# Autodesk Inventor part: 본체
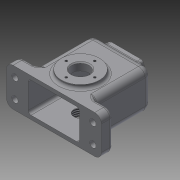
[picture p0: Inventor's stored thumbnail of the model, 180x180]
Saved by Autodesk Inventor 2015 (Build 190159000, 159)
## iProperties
Created: 2023-12
Part Number: 본체
Material: 일반
Document SubType Name: Modeling
Designer: 104-1
Density: 1 g/cm^3
Appearance: 기본값
Mass: 83.567 g
Surface Area: 378.551 cm^2
Volume: 83.567 cm^3
Author: 104-1
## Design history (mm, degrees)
sketch "스케치1"
  geometry: L1 (31, 20)-(-31, 20); L2 (-31, 20)-(-31, -20); L3 (-31, -20)-(31, -20); L4 (31, -20)-(31, 20); L5 (31, 20)-(-31, -20); L6 (-31, 20)-(31, -20); 1 further point
  constraints: 12 end point, 2 midpoint, 2 parallel, 1 horizontal, 1 perpendicular
  dimensions: "d0" = 62 distance of L2.end L3.end; "d1" = 40 distance of L1.end L2.end
extrude "돌출1" new body sketch "스케치1" distance "d2" = 72; taper "d3" = 0 deg
feature "쉘1" dims "d4" = 4
sketch "스케치2"
  geometry: L1 (-31, 20)-(31, 20) reference; L2 (-31, -20)-(-31, 20) reference; L3 (31, -20)-(-31, -20) reference; L4 (31, 20)-(31, -20) reference; L5 (-50, -20)-(50, -20); L6 (50, -20)-(50, 20); L7 (50, 20)-(-50, 20); L8 (-50, 20)-(-50, -20); L9 (-50, -20)-(50, 20); L10 (50, -20)-(-50, 20); 1 further point
  constraints: 12 end point, 2 midpoint, 2 parallel, 1 horizontal, 1 perpendicular
  dimensions: "d5" = 40 distance of L5.end L6.end; "d6" = 100 distance of L6.end L7.end
extrude "돌출2" join sketch "스케치2" distance "d7" = 12; taper "d8" = 0 deg
sketch "스케치4"
  geometry: L1 (-19, -72)-(81, -72) reference; C1 r 20 at (31, -44); 2 further points
  constraints: 1 centre point, 1 midpoint, 1 vertical alignment
  dimensions: "d9" = 40 diameter of C1; "d10" = 28 distance of point (31, -72) C1.centre
extrude "돌출3" join sketch "스케치4" distance "d11" = 4; taper "d12" = 0 deg
sketch "스케치5"
  geometry: C1 r 12 at (31, -44); 1 further point
  constraints: 1 centre point
  dimensions: "d13" = 28 distance of point (31, -72) C1.centre; "d14" = 24 diameter of C1
extrude "돌출4" join sketch "스케치5" distance "d15" = 4; taper "d16" = 0 deg
sketch "스케치6"
  geometry: C1 r 20 at (0, 0) reference; 2 further points
  constraints: 1 coincident
hole "구멍1" sketch "스케치6" at (0, 0) diameter "d17" = 18; stored, may be unused: countersink angle "d21" = 90 deg, drill point angle "d23" = 118 deg; dims "d18" = 6, "d19" = 4, "d20" = 2, "d22" = 8
sketch "스케치7"
  geometry: C1 r 9 at (0, 0) reference; 2 further points
  dimensions: "d24" = 15 distance of C1.centre point (0, 15)
hole "구멍2" sketch "스케치7" at (0, 15) diameter "d25" = 2.459; stored, may be unused: countersink angle "d29" = 90 deg, drill point angle "d31" = 118 deg; dims "d26" = 6, "d27" = 4, "d28" = 2, "d30" = 8.8
sketch "스케치8"
  geometry: C1 r 12 at (0, 0) reference; 2 further points
  constraints: 1 coincident
hole "구멍3" sketch "스케치8" at (0, 0) diameter "d35" = 13.835; stored, may be unused: countersink angle "d39" = 90 deg, drill point angle "d41" = 118 deg; dims "d36" = 32, "d37" = 4, "d38" = 2, "d40" = 10
sketch "스케치9"
  geometry: L1 (0, 0)-(62, 0) reference; L2 (11, -24)-(51, -24); L3 (51, -24)-(51, 0); L4 (51, 0)-(11, 0); L5 (11, 0)-(11, -24); L6 (11, -24)-(51, 0); L7 (51, -24)-(11, 0); C1 r 12 at (31, -44) reference; 3 further points
  constraints: 12 end point, 3 midpoint, 2 parallel, 1 collinear, 1 horizontal, 1 perpendicular, 1 vertical alignment
  dimensions: "d42" = 24 distance of L2.end L3.end; "d43" = 40 distance of L2.start L2.end
extrude "돌출5" join sketch "스케치9" distance "d44" = 4; taper "d45" = 0 deg
sketch "스케치10"
  geometry: L1 (11, -24)-(51, -24) reference; L2 (51, 0)-(11, 0) reference; L3 (31, 0)-(31, -24); 3 further points
  constraints: 2 end point, 2 midpoint, 1 symmetric about line
  dimensions: "d46" = 28 distance of point (45, -6) point (17, -6); "d47" = 6 distance from line of L2 point (17, -6)
hole "구멍4" sketch "스케치10" at (17, -6), (45, -6) diameter "d48" = 2.459; stored, may be unused: countersink angle "d52" = 90 deg, drill point angle "d54" = 118 deg; dims "d49" = 6, "d50" = 4, "d51" = 2, "d53" = 8.8
sketch "스케치11"
  geometry: L1 (-20, 24)-(20, 24) reference; L2 (17.321, 3)-(-17.321, 3); L3 (-17.321, -17)-(17.321, -17); L4 (17.321, 3)-(-17.321, -17); L5 (-17.321, 3)-(17.321, -17); A1 r 20 centre (0, -7) between (17.321, -17) and (17.321, 3); A2 r 20 centre (0, -7) between (-17.321, 3) and (-17.321, -17); 3 further points
  constraints: 8 end point, 4 point on circle, 3 midpoint, 2 centre point, 1 coincident, 1 horizontal, 1 parallel, 1 vertical alignment
  dimensions: "d56" = 31 distance from line of L1 point (0, -7); "d57" = 20 radius of A2; "d58" = 20 distance between parallel lines of L2 L3
extrude "돌출6" join sketch "스케치11" distance "d59" = 4; taper "d60" = 0 deg
sketch "스케치12"
  geometry: L1 (17.321, 3)-(-17.321, 3) reference; L2 (-17.321, -17)-(17.321, -17) reference; L3 (0, -17)-(0, 3); 4 further points
  constraints: 3 midpoint, 2 end point, 1 horizontal alignment, 1 symmetric about line
  dimensions: "d61" = 28 distance of point (-14, -7) point (14, -7)
hole "구멍5" sketch "스케치12" at (14, -7), (-14, -7) diameter "d62" = 2.459; stored, may be unused: countersink angle "d66" = 90 deg, drill point angle "d68" = 118 deg; dims "d63" = 6, "d64" = 4, "d65" = 2, "d67" = 8.8
sketch "스케치13"
  geometry: A1 r 20 centre (0, -7) between (17.321, -17) and (17.321, 3) reference; 2 further points
  constraints: 1 coincident
hole "구멍6" sketch "스케치13" at (0, -7) diameter "d69" = 16; stored, may be unused: countersink angle "d73" = 90 deg, drill point angle "d75" = 118 deg; dims "d70" = 6, "d71" = 4, "d72" = 2, "d74" = 8.8
sketch "스케치14"
  geometry: 2 further points
  dimensions: "d76" = 41 horizontal distance of point (41, -10) point (0, 0); "d77" = 10 vertical distance of point (41, -10) point (0, 0)
hole "구멍7" sketch "스케치14" at (41, -10) diameter "d78" = 6.6; stored, may be unused: countersink angle "d82" = 90 deg, drill point angle "d84" = 118 deg; dims "d79" = 6, "d80" = 11, "d81" = 6.6, "d83" = 8.8
fillet "모깎기1" dims "d91" = 7, "d94" = 3
fillet "모깎기2" dims "d92" = 3
fillet "모깎기3" dims "d96" = 3, "d106" = 7
fillet "모깎기4" dims "d97" = 3
chamfer "모따기1" distance "d98" = 1; stored, may be unused: second distance "d99" = 2, angle "d100" = 45 deg
sketch "스케치15"
  geometry: L1 (-11, 25)-(-11, 1) reference; L2 (26, -15)-(0, -15) reference; 2 further points
  constraints: 1 other
  dimensions: "d102" = 23 distance from line of L1 point (12, 25); "d103" = 40 distance from line of L2 point (12, 25)
feature "엠보싱1" sketch "스케치15" dims "d0" = 62, "d1" = 40, "d104" = 0.5, "d105" = 0
fillet "모깎기5" dims "d107" = 3, "d109" = 5
fillet "모깎기6" dims "d108" = 5
node "솔리드1"
pattern_circular "원형 패턴1" dims angle "d33" = 360 deg
pattern_linear "직사각형 패턴1" dims "d87" = 20, "d90" = 82
